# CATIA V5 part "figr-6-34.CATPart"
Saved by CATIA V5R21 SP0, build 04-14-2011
Part number: Part1
Bounding box of the stored display mesh (mm): x -40.3 to 40.3, y -45.975 to 45.975, z 0 to 40
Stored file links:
  D:\CATIA V5R21 E-RESOURCES\CATIA-V5R21\catia-v5r21-prt\c06-catia-v5r21-prt\c06-catia-v5r21-figr-6-34.CATPart
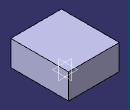
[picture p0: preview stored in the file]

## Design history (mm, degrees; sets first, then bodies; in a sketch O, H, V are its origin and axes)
Body1 (main body)
  Sketch1 on xy-plane, origin (0, 0, 0), H (1, 0, 0), V (0, 1, 0)
    line L1 (-40.2998, 45.9753) -> (40.2998, 45.9753)
    line L2 (40.2998, 45.9753) -> (40.2998, -45.9753)
    line L3 (40.2998, -45.9753) -> (-40.2998, -45.9753)
    line L4 (-40.2998, -45.9753) -> (-40.2998, 45.9753)
    axis line L5 (40.2998, -45.9753) -> (-40.2998, 45.9753)
    horizontal: L1 H, L3 H
    vertical: L2 V, L4 V
    midpoint: O L5
  Pad1: profile Sketch1, direction (0, 0, 1), length 40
